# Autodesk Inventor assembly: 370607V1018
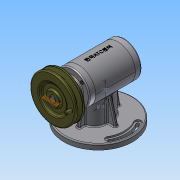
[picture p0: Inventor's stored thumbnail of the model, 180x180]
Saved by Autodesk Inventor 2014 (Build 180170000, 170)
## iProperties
Created: 2017-06
Part Number: 370607V1018
Document SubType Name: Assembly
Designer: NET
Mass: 1417.53 g
Surface Area: 1464.36 cm^2
Volume: 498.031 cm^3
Density: 2.84627 g/cm^3
Author: NET
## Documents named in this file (15)
- C:\Users\NET\Desktop\370607V1018\답안조립품.iam
- C:\Users\NET\Desktop\370607V1018\본체.ipt
- C:\Users\NET\Desktop\370607V1018\본체커버.ipt
- C:\Users\NET\Desktop\370607V1018\앞커버.ipt
- C:\Users\NET\Desktop\370607V1018\볼트 M3x0.5x8.ipt
- C:\Users\NET\Desktop\370607V1018\오일실 12 22 7.ipt
- C:\Users\NET\Desktop\370607V1018\베어링 6201.ipt
- C:\Users\NET\Desktop\370607V1018\뒤커버.ipt
- C:\Users\NET\Desktop\370607V1018\베어링 6202.ipt
- C:\Users\NET\Desktop\370607V1018\편심축.ipt
- C:\Users\NET\Desktop\370607V1018\키 4 x 4 x 18.ipt
- C:\Users\NET\Desktop\370607V1018\V-벨트풀리.ipt
- C:\Users\NET\Desktop\370607V1018\멈춤나사 M3x8.ipt
- C:\Users\NET\Desktop\370607V1018\슬라이드.ipt
- C:\Users\NET\Desktop\370607V1018\스프링-[가변].ipt
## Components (1 placed, 1 different names)
1. V-벨트풀리:1 — 강체:1
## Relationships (1: WeldJoint 1)
- 강체:1 [WeldJoint]: V-벨트풀리:1
